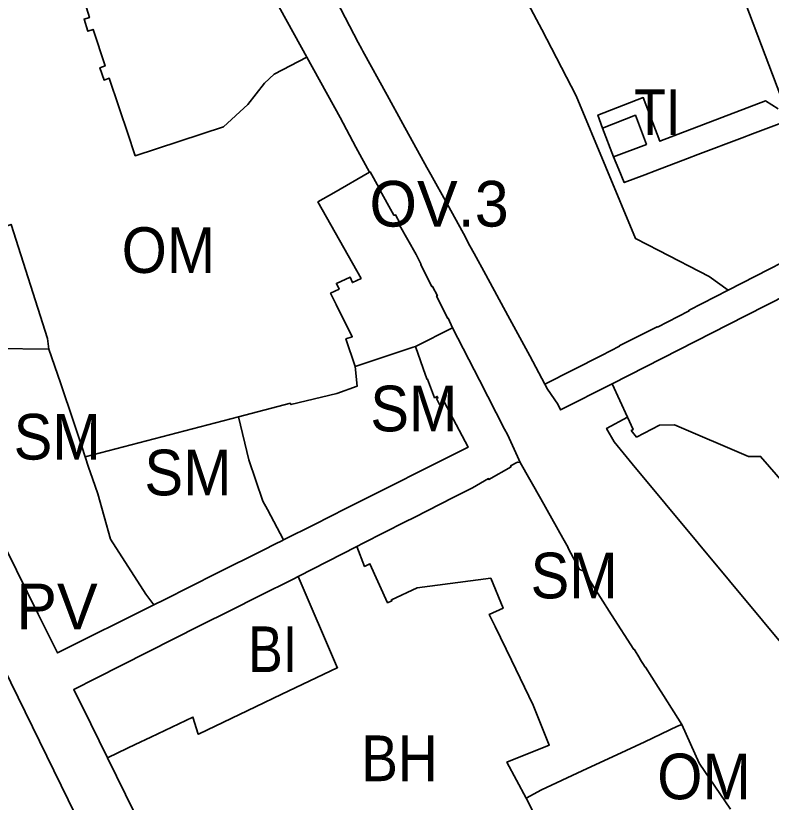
# Model space of a CAD drawing. Extents: x -650451 to -642268, y -1075216 to -1066610.
# Drawn here: x -647599.3 to -647351.3, y -1071003.9 to -1070745.7 of the extents above; entities that cross this region are included whole.
import ezdxf

# ---------------------------------------------------------------- set-up
doc = ezdxf.new("R2010")
doc.units = 0
doc.header["$LTSCALE"] = 6
doc.layers.add('1', color=7, linetype='Continuous', lineweight=35)
doc.layers.add('2', color=7, linetype='Continuous')
doc.layers.add('3', color=7, linetype='Continuous')

msp = doc.modelspace()

# ---------------------------------------------------------------- linework, layer by layer
at = {"layer": '1'}
for p, q in [((-647534.33, -1070703.84), (-647503.76, -1070759.31)), ((-647406.65, -1070782.64), (-647403.1, -1070792.1)), ((-647398.52, -1070877.49), (-647403.51, -1070866.6)), ((-647526.13, -1070877.41), (-647576.469, -1070890.564)), ((-647506.58, -1070929.86), (-647487.33, -1070919.95))]:
    msp.add_line(p, q, dxfattribs=at)
for points in [[(-647425.58, -1070866.7), (-647430.54, -1070857.41), (-647437.79, -1070844.12), (-647445, -1070830.82), (-647448.84, -1070823.79), (-647450.23, -1070821.25), (-647452.32, -1070817.27), (-647457.71, -1070807.52), (-647463.04, -1070797.92), (-647464.3, -1070795.6), (-647472.17, -1070781.27), (-647477.34, -1070771.84), (-647485.35, -1070757.35), (-647485.68, -1070756.73), (-647486.84, -1070754.54), (-647502.59, -1070724.13), (-647513.59, -1070702.8), (-647518.19, -1070693.93), (-647523.27, -1070680.11)], [(-647365.48, -1070835.85), (-647371.72, -1070831.32), (-647388.21, -1070822.82), (-647395.85, -1070818.88), (-647415.3, -1070772.06), (-647426.62, -1070750.25), (-647431.13, -1070741.87), (-647433.02, -1070737.37), (-647433.64, -1070735.74), (-647436.73, -1070727.66), (-647446.14, -1070731.2), (-647450.01, -1070721.16), (-647461.46, -1070691.58), (-647460.76, -1070691.31), (-647461.99, -1070688.14), (-647462.69, -1070688.41), (-647463.1, -1070687.34), (-647459.14, -1070685.83), (-647459.02, -1070685.79), (-647447.76, -1070681.5)], [(-647503.76, -1070759.31), (-647514.49, -1070764.93), (-647517.61, -1070767.89), (-647523.07, -1070774.86), (-647531.05, -1070782.23), (-647560.06, -1070791.72), (-647560.38, -1070790.77), (-647562.274, -1070785.087), (-647568.55, -1070766.29), (-647570.27, -1070766.86), (-647571.63, -1070762.82), (-647569.92, -1070762.24), (-647573.88, -1070750.25), (-647575.58, -1070750.83), (-647576.81, -1070746.86), (-647575.09, -1070746.33), (-647578.79, -1070734.33), (-647583.38, -1070720.9), (-647583.221, -1070720.205)], [(-647346.96, -1070775.41), (-647365.94, -1070725.08)], [(-647483.16, -1070797.07), (-647487.67, -1070788.86), (-647492.81, -1070779.18), (-647503.76, -1070759.31)], [(-647715.3, -1070769.09), (-647708.31, -1070783.21), (-647708.04, -1070783.07), (-647706.21, -1070786.87), (-647704.498, -1070790.24), (-647705.06, -1070790.51), (-647701.56, -1070797.79), (-647701.32, -1070798.28), (-647701.41, -1070798.33), (-647694.09, -1070813.56), (-647693.96, -1070813.49), (-647689.95, -1070821.13), (-647689.08, -1070820.64), (-647686.2, -1070826.54), (-647687.12, -1070826.94), (-647681.06, -1070839.75), (-647660.03, -1070856.69), (-647649.83, -1070864.82), (-647638.54, -1070887.82), (-647572.64, -1071022.41), (-647567.83, -1071032.07), (-647565.56, -1071036.69), (-647553.4, -1071061.35), (-647539.817, -1071089.199)], [(-647406.65, -1070782.64), (-647408.18, -1070778.37), (-647393.32, -1070772.59), (-647387.9, -1070786.93), (-647353.16, -1070773.63), (-647349.01, -1070776.26)], [(-647406.65, -1070782.64), (-647395.86, -1070778.43), (-647392.29, -1070787.98), (-647403.1, -1070792.1)], [(-647365.48, -1070835.85), (-647334.27, -1070819.86), (-647332.51, -1070817.97), (-647332.25, -1070813.72), (-647345.18, -1070779.89), (-647357.48, -1070784.55), (-647360.82, -1070785.82), (-647375.41, -1070791.35), (-647378.76, -1070792.61), (-647389.45, -1070796.66), (-647392.8, -1070797.93), (-647399.56, -1070800.5), (-647401.36, -1070796.2), (-647403.1, -1070792.1)], [(-647487.91, -1070860.91), (-647490.92, -1070851.82), (-647488.8, -1070851.12), (-647491.19, -1070846.49), (-647492.48, -1070843.88), (-647494.1, -1070840.58), (-647495.93, -1070836.86), (-647493.16, -1070835.5), (-647494.03, -1070833.64), (-647489.55, -1070831.53), (-647488.75, -1070833.37), (-647485.9, -1070832), (-647500.07, -1070806.87), (-647494.88, -1070803.86), (-647483.16, -1070797.07)], [(-647483.16, -1070797.07), (-647482.97, -1070796.97), (-647480.13, -1070802.09), (-647480.23, -1070802.15), (-647475.13, -1070811.22), (-647474.99, -1070811.14), (-647474.94, -1070811.23), (-647474.66, -1070811.07), (-647472.93, -1070814.16), (-647473.21, -1070814.31), (-647473.16, -1070814.4), (-647473.3, -1070814.47), (-647467.89, -1070824.15), (-647466.24, -1070827.41), (-647466.33, -1070827.46), (-647462.65, -1070834.74), (-647462.44, -1070834.62), (-647460.89, -1070837.67), (-647461.12, -1070837.79), (-647457.42, -1070845.12), (-647457.31, -1070845.06), (-647455.88, -1070848.19), (-647468.04, -1070854.31)], [(-647588.4, -1070855.25), (-647588.89, -1070851.67), (-647600.8, -1070814.27), (-647647.571, -1070829.133)], [(-647300.07, -1070911.99), (-647294.73, -1070906.32), (-647293.09, -1070897.18), (-647293.7, -1070893.99), (-647299.98, -1070891.49), (-647318.68, -1070842.72), (-647316.06, -1070835.75), (-647318.44, -1070829.76), (-647321.01, -1070827.14), (-647324.15, -1070826.29), (-647331.02, -1070829.74), (-647345.71, -1070837.13), (-647359.71, -1070844.27), (-647403.51, -1070866.6)], [(-647365.48, -1070835.85), (-647378.2, -1070842.39), (-647378.15, -1070842.48), (-647378.51, -1070842.66), (-647378.45, -1070842.77), (-647388.69, -1070847.95), (-647388.75, -1070847.82), (-647395.98, -1070851.48), (-647401.21, -1070854.14), (-647401.15, -1070854.25), (-647406.99, -1070857.23), (-647425.58, -1070866.7)], [(-647455.88, -1070848.19), (-647447.05, -1070865.4), (-647438.82, -1070881.43), (-647437.9, -1070883.23), (-647434.61, -1070890.49), (-647433.74, -1070892.4)], [(-647511.37, -1070917.79), (-647501.26, -1070912.72), (-647490.93, -1070907.5), (-647450.8, -1070887.42), (-647458.69, -1070872.44), (-647460.19, -1070873.32), (-647461.15, -1070871.43), (-647460.72, -1070871.21), (-647460.94, -1070870.74), (-647461.77, -1070871.13), (-647464.12, -1070865.08), (-647464.27, -1070865.14), (-647464.79, -1070863.76), (-647468.04, -1070854.31)], [(-647468.04, -1070854.31), (-647468.8, -1070854.56), (-647487.91, -1070860.91)], [(-647629.92, -1070865.35), (-647618.01, -1070859.42), (-647611.3, -1070854.9), (-647605.64, -1070854.99), (-647588.4, -1070855.25)], [(-647588.4, -1070855.25), (-647584.6, -1070866.3), (-647580.22, -1070879.3), (-647577.59, -1070887.19), (-647576.469, -1070890.564)], [(-647526.13, -1070877.41), (-647509.1, -1070872.96), (-647508.96, -1070873.41), (-647493.9, -1070869.71), (-647487.16, -1070867.32), (-647487.91, -1070860.91)], [(-647403.51, -1070866.6), (-647420.46, -1070875.15), (-647421.35, -1070873.29), (-647424.79, -1070868.34), (-647425.58, -1070866.7)], [(-647511.37, -1070917.79), (-647516.66, -1070907.8), (-647518.12, -1070905.05), (-647522.74, -1070891.48), (-647526.13, -1070877.41)], [(-647283.54, -1070954.02), (-647290.28, -1070945.89), (-647293.51, -1070942.01), (-647326.51, -1070969.42), (-647338.57, -1070953.63), (-647343.34, -1070957.27), (-647396.9, -1070892.8), (-647402.82, -1070885.66), (-647405.34, -1070881.23), (-647398.52, -1070877.49)], [(-647398.52, -1070877.49), (-647396.63, -1070881.62), (-647397.24, -1070881.95), (-647395.52, -1070884.04), (-647387.99, -1070880.11), (-647383.09, -1070880.09), (-647358.76, -1070890.4), (-647354.79, -1070890.4), (-647327.54, -1070921.72), (-647323.84, -1070923.35), (-647321.91, -1070922.61), (-647317.93, -1070918.75), (-647314.33, -1070915.95), (-647305.3, -1070907.01), (-647300.07, -1070911.99)], [(-647576.469, -1070890.564), (-647575.35, -1070893.91), (-647574.09, -1070897.7), (-647572.32, -1070902.72), (-647568.2, -1070917.54), (-647556.52, -1070935.59), (-647553.94, -1070939.11)], [(-647487.33, -1070919.95), (-647485.28, -1070918.92), (-647471.47, -1070911.94), (-647468.53, -1070910.45), (-647455.5, -1070903.83), (-647449.35, -1070900.71), (-647444.1, -1070897.7), (-647443.95, -1070898), (-647436.7, -1070893.79), (-647436.84, -1070893.51), (-647434.6, -1070892.27), (-647433.74, -1070892.4)], [(-647433.74, -1070892.4), (-647426.98, -1070904.3), (-647419.66, -1070917.2), (-647417.91, -1070920.29), (-647418.03, -1070920.36), (-647414.25, -1070927.53), (-647413, -1070927.92), (-647412.89, -1070928.07), (-647412.82, -1070928.02), (-647410.91, -1070931.03), (-647410.99, -1070931.08), (-647403.69, -1070942.39), (-647396.42, -1070953.78), (-647396.34, -1070953.73), (-647394.42, -1070956.71), (-647394.5, -1070956.76), (-647394.44, -1070956.9), (-647392.67, -1070959.61), (-647392.59, -1070959.57), (-647388.38, -1070966.11), (-647388.47, -1070966.17), (-647386.68, -1070968.95), (-647380.69, -1070978.37)], [(-647606.18, -1070913.28), (-647599.03, -1070927.71), (-647591.86, -1070942.2), (-647585.55, -1070954.94), (-647553.94, -1070939.11)], [(-647553.94, -1070939.11), (-647550.59, -1070937.45), (-647533.31, -1070928.79), (-647518.08, -1070921.16), (-647513.96, -1070919.09), (-647511.91, -1070918.07), (-647511.37, -1070917.79)], [(-647431.74, -1071002.56), (-647438.05, -1070990.74), (-647424.16, -1070985.19), (-647429.44, -1070972.06), (-647436.58, -1070957.29), (-647441.9, -1070946.28), (-647442.33, -1070945.38), (-647443.84, -1070942.26), (-647439.33, -1070940.28), (-647443.36, -1070930.41), (-647467.47, -1070933.53), (-647475.97, -1070937.46), (-647475.82, -1070937.77), (-647477.21, -1070938.44), (-647483.02, -1070925.66), (-647484.78, -1070926.54), (-647487.33, -1070919.95)], [(-647569.19, -1070989.36), (-647574.6, -1070978.25), (-647580.21, -1070966.91), (-647572.81, -1070963.21), (-647538.96, -1070946.03), (-647528.59, -1070940.88), (-647519.72, -1070936.439), (-647507.79, -1070930.48), (-647506.776, -1070929.958), (-647506.58, -1070929.86)], [(-647569.19, -1070989.36), (-647562.56, -1070986.2), (-647560.03, -1070984.99), (-647554.89, -1070982.54), (-647541.12, -1070975.97), (-647539.38, -1070981.6), (-647539.08, -1070981.46), (-647520.58, -1070972.61), (-647511.96, -1070968.48), (-647493.79, -1070959.8), (-647493.71, -1070959.89), (-647506.58, -1070929.86)], [(-647380.69, -1070978.37), (-647382.05, -1070979.01), (-647392.83, -1070984.14), (-647401.93, -1070988.34), (-647410.26, -1070992.23), (-647413.35, -1070993.67), (-647426.7, -1070999.91), (-647431.74, -1071002.56)], [(-647380.69, -1070978.37), (-647374.95, -1070991.15), (-647364.66, -1071006.25)], [(-647560.28, -1071007.46), (-647569.19, -1070989.36)], [(-647431.74, -1071002.56), (-647423.84, -1071018.04), (-647421.89, -1071021.82), (-647418.88, -1071028.01)]]:
    msp.add_lwpolyline(points, dxfattribs=at)

# ---------------------------------------------------------------- texts
at = {"layer": '2'}
for s, width, p in [('TI', 0.85, (-647396.268, -1070784.943)), ('SM', 0.95, (-647482.899, -1070882.183)), ('SM', 0.95, (-647599.957, -1070891.444)), ('SM', 0.95, (-647430.297, -1070937.008)), ('BI', 0.85, (-647523.004, -1070961.222)), ('BH', 0.9, (-647485.863, -1070997.022)), ('OM', 0.95, (-647388.72, -1071002.97))]:
    msp.add_text(s, height=15, dxfattribs=dict(at, width=width)).set_placement(p)
for s, p in [('OV.3', (-647483.17, -1070814.97)), ('PV', (-647599.1, -1070947.176))]:
    msp.add_text(s, height=15, dxfattribs=at).set_placement(p)
at = {"layer": '3', "width": 0.95}
for s, p in [('OM', (-647564.486, -1070830.183)), ('SM', (-647557.039, -1070903.195))]:
    msp.add_text(s, height=15, dxfattribs=at).set_placement(p)

doc.saveas('drawing.dxf')
